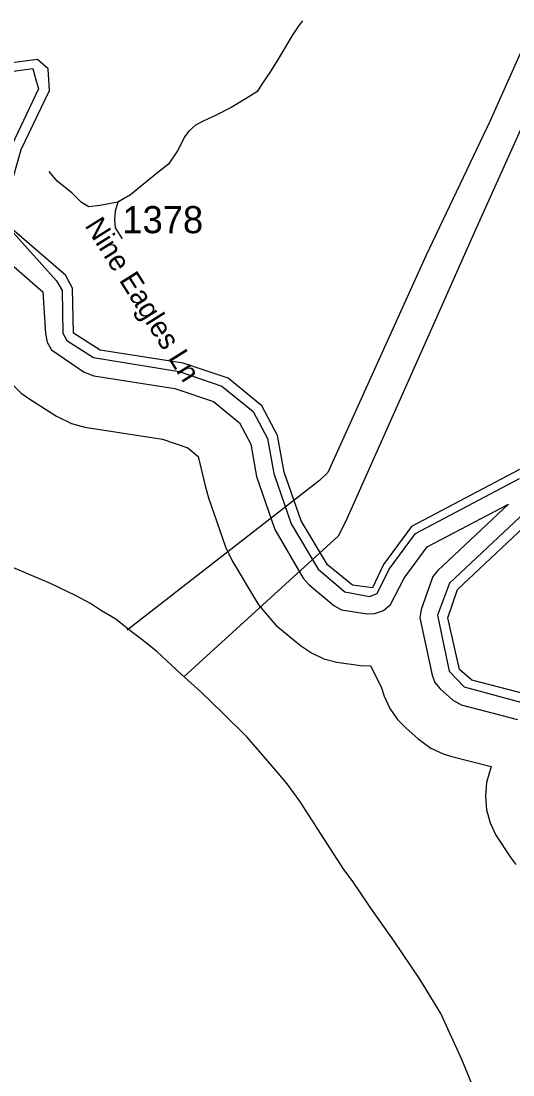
# Model space of a CAD drawing. Extents: x 1383679 to 1536984, y 460658 to 651027.
# Drawn here: x 1388989 to 1391254, y 505838 to 510693 of the extents above; entities that cross this region are included whole.
import ezdxf

# ---------------------------------------------------------------- set-up
doc = ezdxf.new("R2010")
doc.units = 0
for name, color, linetype in [('Exist Boundary Political StateLine', 7, 'Continuous'), ('Exist Hydrographic Bay Label', 7, 'Continuous'), ('Exist Hydrographic Buffer Line', 7, 'Continuous'), ('Exist Road Non-System Type 51', 7, 'Continuous'), ('Exist Road Non-System Type 51 Label', 7, 'Continuous'), ('Exist Road Secondary Type 51 Attributed', 7, 'Continuous'), ('Exist Road Secondary Type 51 Number Label', 7, 'Continuous'), ('Exist Utilities Electrical Transmission Line', 7, 'Continuous')]:
    doc.layers.add(name, color=color, linetype=linetype)

msp = doc.modelspace()

# ---------------------------------------------------------------- linework, layer by layer
at = {"layer": 'Exist Boundary Political StateLine'}
for points in [[(1389545.2, 507844.6), (1389490, 507885.8), (1389425.2, 507937.1), (1389360, 507976.6), (1389308.7, 508009.7), (1389239.4, 508047.1), (1389124.4, 508101.4), (1389013.3, 508149.9), (1388951.8, 508175.1)], [(1391099.7, 505711.4), (1391017.7, 505909.4), (1390922.1, 506121.4), (1390825.2, 506279.4), (1390706.9, 506454), (1390599.9, 506606.3), (1390513.3, 506733.4), (1390475.7, 506784.9), (1390369, 506949.1), (1390272.1, 507099.3), (1390213.7, 507178.5), (1390164.9, 507237.5), (1390030.2, 507394.5), (1389916.4, 507506.8), (1389816.5, 507602.9), (1389726.1, 507684.9), (1389616.1, 507787.2), (1389545.2, 507844.6)]]:
    msp.add_lwpolyline(points, dxfattribs=at)
at = {"layer": 'Exist Hydrographic Bay Label'}
for points in [[(1388935.5, 509911.2), (1388989.5, 510100.4), (1389119.5, 510373.5), (1389113.4, 510472.1), (1389064.4, 510515.8), (1388805.5, 510481.6)], [(1391284.4, 508626.5), (1390787.3, 508364), (1390658.4, 508189.4), (1390606.4, 508082.1), (1390514.4, 508093.7), (1390400.4, 508188), (1390279.4, 508390.7), (1390200.4, 508615.4), (1390170.4, 508783.4), (1390098.4, 508919.5), (1389942.4, 509047.3), (1389735.5, 509117.1), (1389353.4, 509177.3), (1389230.4, 509255.3), (1389226.4, 509462.2), (1389193.4, 509521.9), (1388948.5, 509733.6)], [(1391313.4, 507592), (1391064.4, 507656), (1391007.4, 507706.4), (1390953.3, 507943.9), (1390998.3, 508074.2), (1391380.3, 508434.2)]]:
    msp.add_lwpolyline(points, dxfattribs=at)
at = {"layer": 'Exist Hydrographic Buffer Line'}
for points in [[(1388805, 510442.1), (1389042.7, 510473.5), (1389053, 510438.8), (1389070.1, 510381.1), (1388944.6, 510117.3)], [(1388939.7, 509733.4), (1389153, 509496.1), (1389177.8, 509451.3), (1389181.6, 509254.3), (1389200.2, 509221.3), (1389323.2, 509143.3), (1389717.1, 509077.9), (1389914, 509011.5), (1390058, 508893.4), (1390123.3, 508770), (1390152.2, 508608.2), (1390232.9, 508377.2), (1390357.3, 508167.2), (1390480.1, 508062.7), (1390592.6, 508042.1), (1390628.3, 508056.1), (1390683.9, 508168.4), (1390805.3, 508332.6), (1391284.3, 508585.6)], [(1388847.7, 509656.3), (1389089.9, 509444.9), (1389101.7, 509252.7), (1389108.8, 509214), (1389129.6, 509177.9), (1389280.4, 509075.7), (1389323.8, 509058.9), (1389697.9, 509000), (1389874.5, 508940.4), (1389994.9, 508841.8), (1390046.7, 508743.6), (1390073.5, 508594.1), (1390157.5, 508350.6), (1390288.6, 508126.2), (1390315.2, 508095.3), (1390429.2, 508001), (1390464.6, 507980.7), (1390582.4, 507962.8), (1390618.4, 507963.6), (1390657.6, 507977.9), (1390689.6, 508004.6), (1390752.7, 508126.8), (1390858.8, 508270.4), (1391232.5, 508467.7), (1390907.2, 508161.3), (1390885.6, 508133.9), (1390831.2, 507982.8), (1390824.6, 507943.6), (1390881.6, 507679.5), (1390894.6, 507646.2), (1390919.1, 507616.2), (1390976.1, 507565.8), (1391014.6, 507543), (1391274.7, 507475.5)], [(1388945.8, 509023.6), (1388990.2, 508979.3), (1389028.9, 508951), (1389151.9, 508873), (1389221.5, 508838.8), (1389282.1, 508822.5), (1389640.5, 508766.1), (1389756.3, 508727), (1389805.3, 508686.8), (1389837.3, 508551.8), (1389852, 508495.7), (1389931.1, 508271), (1389961.5, 508206), (1390082.5, 508003.3), (1390162.2, 507910.3), (1390276.2, 507816), (1390325.6, 507781.7), (1390382.5, 507755.2), (1390443.1, 507738.9), (1390552.2, 507724.6), (1390597.6, 507721.8), (1390647.5, 507626.3), (1390660.3, 507583), (1390686.8, 507526.2), (1390722.8, 507474.7), (1390760.1, 507436.4), (1390817.1, 507386), (1390875.6, 507344), (1390932.5, 507317.5), (1390965.9, 507307.1), (1391154.1, 507258.7), (1391132.1, 507184.4), (1391126.6, 507121.9), (1391132.1, 507059.4), (1391148.3, 506998.8), (1391174.8, 506941.9), (1391243.9, 506837.7), (1391266.8, 506807.3)], [(1391336.3, 508455.6), (1390962.1, 508103.1), (1390906.7, 507956.7), (1390959.6, 507697.3), (1391029.1, 507625.8), (1391294.7, 507552.9)]]:
    msp.add_lwpolyline(points, dxfattribs=at)
at = {"layer": 'Exist Road Non-System Type 51'}
for points in [[(1389434.5, 509858.8), (1389351.9, 509842.3), (1389300.8, 509837.6), (1389266.8, 509856.4), (1389223, 509901.3), (1389155, 509955.5), (1389118.5, 510000.3)], [(1389434.5, 509858.8), (1389422.4, 509816.3), (1389420, 509778.6), (1389422.4, 509740.9), (1389454, 509689)]]:
    msp.add_lwpolyline(points, dxfattribs=at)
at = {"layer": 'Exist Road Secondary Type 51 Attributed'}
msp.add_lwpolyline([(1390284.7, 510693.6), (1390267.7, 510671.8), (1390237.1, 510625.4), (1390202.5, 510566.6), (1390170, 510513.2), (1390134.2, 510455.8), (1390100.6, 510406), (1390081.9, 510377.5), (1390075, 510366.8), (1390025.2, 510335.2), (1389957.2, 510295.1), (1389886.7, 510259.8), (1389828.3, 510231.5), (1389791.9, 510212.6), (1389760.3, 510184.3), (1389743.3, 510160.7), (1389709.2, 510094.7), (1389667.9, 510033.3), (1389619.3, 509995.6), (1389492.9, 509891.8), (1389434.5, 509858.8)], dxfattribs=at)
at = {"layer": 'Exist Utilities Electrical Transmission Line'}
for points in [[(1393398.6, 515176.5), (1393091.3, 514508.2), (1392729, 513727.5), (1392247.3, 512691), (1391997.6, 512133.9), (1391750.3, 511600.6), (1391748.2, 511596.9), (1391727.1, 511539.3), (1391550.7, 511136.6), (1391147.6, 510230.5), (1390854.7, 509614.3), (1390401.7, 508613.2), (1390362.9, 508576.1), (1389477.4, 507887.6)], [(1393541.6, 515156.2), (1393249.1, 514497), (1392872, 513672.4), (1392398.8, 512663.9), (1392124.1, 512059.1), (1391500.5, 510655.4), (1391316.2, 510255.2), (1391288.9, 510191.7), (1391079.1, 509727.7), (1390860.8, 509234), (1390483, 508385.4), (1390449.6, 508320.1), (1389738.2, 507671.5)]]:
    msp.add_lwpolyline(points, dxfattribs=at)

# ---------------------------------------------------------------- texts
at = {"layer": 'Exist Road Non-System Type 51 Label'}
msp.add_text('Nine Eagles Ln', height=95, rotation=302.1802, dxfattribs=at).set_placement((1389280.2, 509750.5))
at = {"layer": 'Exist Road Secondary Type 51 Number Label'}
msp.add_text('1378', height=125, dxfattribs=at).set_placement((1389455.6, 509715.4))

doc.saveas('drawing.dxf')
